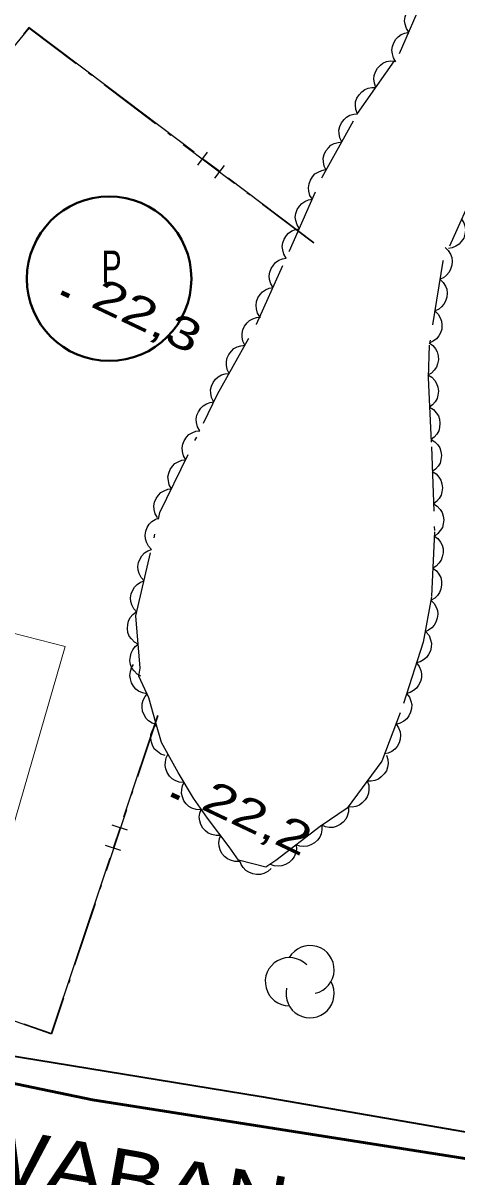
# Model space of a CAD drawing. Extents: x 356765 to 358572, y 5103174 to 5104650.
# Drawn here: x 357365.7 to 357385.9, y 5103762.5 to 5103816.2 of the extents above; entities that cross this region are included whole.
import ezdxf

# ---------------------------------------------------------------- set-up
doc = ezdxf.new("R2010")
doc.units = 0
doc.header["$LTSCALE"] = 0.6
doc.linetypes.add('DOT_DASHED', pattern=[7.7, 5, -1.2, 0.3, -1.2])
for name, color, linetype, lineweight in [('19', 7, 'Continuous', 13), ('21', 7, 'Continuous', 53), ('22', 7, 'Continuous', 35), ('3', 7, 'Continuous', 140), ('37', 7, 'Continuous', 13), ('38', 7, 'Continuous', 40), ('44', 7, 'Continuous', 25)]:
    doc.layers.add(name, color=color, linetype=linetype, lineweight=lineweight)

msp = doc.modelspace()

# ---------------------------------------------------------------- linework, layer by layer
at = {"layer": '19'}
msp.add_lwpolyline([(357362.8, 5103788.4), (357367.66, 5103787.16), (357362.28, 5103768.59)], dxfattribs=at)
at = {"layer": '21'}
msp.add_lwpolyline([(357338.61, 5103773.13), (357340.11, 5103772.62), (357343.3, 5103771.76), (357350.78, 5103769.83), (357368.94, 5103766.05), (357392.09, 5103762.41), (357416.79, 5103758.21), (357441.26, 5103754.15), (357468.58, 5103749.26), (357504.23, 5103742.99), (357523.34, 5103739.7), (357536.22, 5103737.01), (357542.95, 5103734.88), (357550.23, 5103731.38), (357559.17, 5103726.82), (357569.84, 5103720.84), (357583.91, 5103712.01), (357595.28, 5103704.43), (357600.89, 5103700.45), (357609.42, 5103694), (357620.2, 5103685.76)], dxfattribs=at)
at = {"layer": '22'}
msp.add_lwpolyline([(357366.39, 5103817.9), (357352.43, 5103801.73), (357349.01, 5103796), (357343.68, 5103784.65), (357339.63, 5103776.15), (357339.17, 5103775.09), (357339.32, 5103774.54), (357339.69, 5103774.25), (357340.1, 5103774.03), (357347.23, 5103771.98), (357356.47, 5103769.58), (357363.96, 5103768.3), (357376.79, 5103766.21), (357395.27, 5103763.01), (357430.46, 5103757.15), (357465, 5103751.32), (357465.88, 5103751.18), (357468.95, 5103750.64), (357513.48, 5103742.84)], dxfattribs=at)
at = {"layer": '3'}
for p, q in [((357367.49, 5103803.65), (357367.85, 5103803.48)), ((357372.62, 5103780.27), (357372.98, 5103780.1))]:
    msp.add_line(p, q, dxfattribs=at)
at = {"layer": '37', "lineweight": 25}
for p, q in [((357373.67, 5103810.18), (357369.68, 5103813.19)), ((357373.84, 5103809.58), (357374.29, 5103810.18)), ((357374.86, 5103809.28), (357374.06, 5103809.88)), ((357374.64, 5103808.98), (357375.09, 5103809.57)), ((357379.25, 5103805.96), (357375.26, 5103808.97)), ((357371.96, 5103783.95), (357370.38, 5103779.21)), ((357370.57, 5103778.61), (357369.86, 5103778.85)), ((357370.22, 5103778.73), (357369.9, 5103777.78)), ((357370.26, 5103777.66), (357369.54, 5103777.9)), ((357369.74, 5103777.31), (357368.16, 5103772.57))]:
    msp.add_line(p, q, dxfattribs=at)
at = {"layer": '37', "linetype": 'DOT_DASHED', "lineweight": 25}
for points in [[(357379.24, 5103805.94), (357365.98, 5103815.96), (357350.85, 5103797.63), (357349.13, 5103795.01), (357343.36, 5103779.3), (357342.98, 5103776.7), (357343.51, 5103775.15), (357358.16, 5103771.26)], [(357371.98, 5103783.94), (357367.03, 5103769.11), (357362.72, 5103770.63)]]:
    msp.add_lwpolyline(points, dxfattribs=at)
at = {"layer": '37', "lineweight": 25}
for points in [[(357369.68, 5103813.19), (357365.98, 5103815.99), (357365.72, 5103815.68)], [(357368.16, 5103772.57), (357367.02, 5103769.14), (357365.75, 5103769.58)]]:
    msp.add_lwpolyline(points, dxfattribs=at)
at = {"layer": '38'}
msp.add_circle((357369.7129, 5103804.2931), 3.8299, dxfattribs=at)
at = {"layer": '44', "linetype": 'DOT_DASHED'}
for points in [[(357371.1, 5103785.78), (357371.16, 5103786.16), (357370.96, 5103788.6), (357372.08, 5103793.41), (357374.76, 5103798.91), (357376.58, 5103802.17), (357378.11, 5103805.59), (357379.63, 5103809.02), (357381.28, 5103811.98), (357383.23, 5103814.78), (357384.59, 5103817.91)], [(357386.78, 5103808.54), (357385.25, 5103805.11), (357384.62, 5103801.19), (357384.56, 5103799.67), (357384.72, 5103796.47), (357384.86, 5103792.51), (357384.72, 5103789.48), (357384.33, 5103787.37), (357383.27, 5103784.07), (357382.41, 5103781.83), (357380.79, 5103779.63), (357379.53, 5103778.78), (357377.48, 5103777.2), (357377.01, 5103776.89), (357375.73, 5103777.21), (357375.3, 5103777.83), (357374.29, 5103779.17), (357373.64, 5103780.11), (357372.93, 5103781.29), (357372.15, 5103782.69), (357371.89, 5103783.61), (357371.56, 5103784.77), (357371.1, 5103785.78)]]:
    msp.add_lwpolyline(points, dxfattribs=at)
at = {"layer": '44'}
for points in [[(357383.66, 5103815.77), (357383.55, 5103815.94), (357383.49, 5103816.14), (357383.47, 5103816.3), (357383.5, 5103816.48), (357383.56, 5103816.65), (357383.66, 5103816.81), (357383.76, 5103816.94), (357383.91, 5103817.04), (357384.08, 5103817.11), (357384.26, 5103817.14)], [(357383.06, 5103814.39), (357382.95, 5103814.57), (357382.9, 5103814.76), (357382.87, 5103814.93), (357382.9, 5103815.1), (357382.96, 5103815.28), (357383.06, 5103815.44), (357383.17, 5103815.56), (357383.31, 5103815.66), (357383.48, 5103815.73), (357383.66, 5103815.77)], [(357382.13, 5103813.2), (357382.06, 5103813.4), (357382.04, 5103813.6), (357382.05, 5103813.76), (357382.11, 5103813.93), (357382.2, 5103814.09), (357382.34, 5103814.23), (357382.46, 5103814.33), (357382.63, 5103814.4), (357382.81, 5103814.44), (357382.99, 5103814.43)], [(357381.27, 5103811.97), (357381.2, 5103812.17), (357381.18, 5103812.37), (357381.19, 5103812.53), (357381.25, 5103812.7), (357381.35, 5103812.86), (357381.48, 5103813), (357381.61, 5103813.1), (357381.77, 5103813.16), (357381.95, 5103813.2), (357382.13, 5103813.2)], [(357380.54, 5103810.66), (357380.45, 5103810.85), (357380.42, 5103811.05), (357380.41, 5103811.21), (357380.45, 5103811.38), (357380.53, 5103811.55), (357380.65, 5103811.7), (357380.76, 5103811.82), (357380.92, 5103811.9), (357381.1, 5103811.96), (357381.27, 5103811.97)], [(357379.81, 5103809.35), (357379.72, 5103809.54), (357379.69, 5103809.74), (357379.68, 5103809.9), (357379.72, 5103810.07), (357379.8, 5103810.24), (357379.92, 5103810.39), (357380.03, 5103810.51), (357380.19, 5103810.59), (357380.37, 5103810.64), (357380.54, 5103810.66)], [(357379.18, 5103807.99), (357379.06, 5103808.17), (357379.01, 5103808.37), (357378.99, 5103808.53), (357379.02, 5103808.71), (357379.08, 5103808.88), (357379.18, 5103809.04), (357379.29, 5103809.17), (357379.44, 5103809.26), (357379.61, 5103809.33), (357379.78, 5103809.37)], [(357378.57, 5103806.62), (357378.46, 5103806.8), (357378.4, 5103807), (357378.38, 5103807.16), (357378.41, 5103807.33), (357378.47, 5103807.51), (357378.58, 5103807.67), (357378.68, 5103807.79), (357378.83, 5103807.89), (357379, 5103807.96), (357379.18, 5103807.99)], [(357377.96, 5103805.25), (357377.85, 5103805.43), (357377.8, 5103805.63), (357377.77, 5103805.79), (357377.8, 5103805.96), (357377.86, 5103806.14), (357377.97, 5103806.3), (357378.07, 5103806.42), (357378.22, 5103806.52), (357378.39, 5103806.59), (357378.57, 5103806.62)], [(357386.12, 5103807.07), (357386.23, 5103806.89), (357386.29, 5103806.7), (357386.31, 5103806.53), (357386.28, 5103806.36), (357386.22, 5103806.18), (357386.11, 5103806.02), (357386.01, 5103805.9), (357385.86, 5103805.8), (357385.69, 5103805.73), (357385.51, 5103805.7)], [(357385.35, 5103805.75), (357385.5, 5103805.61), (357385.61, 5103805.43), (357385.67, 5103805.28), (357385.69, 5103805.1), (357385.67, 5103804.92), (357385.61, 5103804.74), (357385.54, 5103804.59), (357385.42, 5103804.46), (357385.28, 5103804.34), (357385.11, 5103804.27)], [(357377.35, 5103803.88), (357377.24, 5103804.06), (357377.18, 5103804.26), (357377.16, 5103804.42), (357377.19, 5103804.59), (357377.25, 5103804.77), (357377.36, 5103804.93), (357377.46, 5103805.05), (357377.61, 5103805.15), (357377.78, 5103805.22), (357377.96, 5103805.25)], [(357385.11, 5103804.27), (357385.27, 5103804.12), (357385.37, 5103803.95), (357385.43, 5103803.8), (357385.45, 5103803.62), (357385.43, 5103803.44), (357385.37, 5103803.25), (357385.3, 5103803.11), (357385.19, 5103802.98), (357385.04, 5103802.86), (357384.88, 5103802.79)], [(357376.73, 5103802.51), (357376.62, 5103802.69), (357376.57, 5103802.89), (357376.55, 5103803.05), (357376.58, 5103803.23), (357376.64, 5103803.4), (357376.75, 5103803.56), (357376.85, 5103803.68), (357377, 5103803.78), (357377.17, 5103803.85), (357377.35, 5103803.88)], [(357376.03, 5103801.19), (357375.94, 5103801.38), (357375.9, 5103801.58), (357375.9, 5103801.74), (357375.94, 5103801.91), (357376.02, 5103802.08), (357376.14, 5103802.23), (357376.25, 5103802.34), (357376.41, 5103802.43), (357376.58, 5103802.48), (357376.76, 5103802.5)], [(357384.88, 5103802.79), (357385.03, 5103802.64), (357385.13, 5103802.47), (357385.19, 5103802.31), (357385.21, 5103802.14), (357385.2, 5103801.95), (357385.14, 5103801.77), (357385.07, 5103801.63), (357384.95, 5103801.5), (357384.8, 5103801.38), (357384.64, 5103801.31)], [(357384.62, 5103801.31), (357384.79, 5103801.18), (357384.91, 5103801.02), (357384.99, 5103800.88), (357385.03, 5103800.7), (357385.04, 5103800.52), (357385, 5103800.33), (357384.95, 5103800.18), (357384.85, 5103800.03), (357384.72, 5103799.9), (357384.57, 5103799.81)], [(357375.3, 5103799.88), (357375.21, 5103800.07), (357375.17, 5103800.27), (357375.17, 5103800.43), (357375.21, 5103800.6), (357375.29, 5103800.77), (357375.41, 5103800.92), (357375.52, 5103801.04), (357375.68, 5103801.12), (357375.85, 5103801.17), (357376.03, 5103801.19)], [(357374.57, 5103798.57), (357374.48, 5103798.76), (357374.44, 5103798.96), (357374.43, 5103799.12), (357374.48, 5103799.29), (357374.55, 5103799.46), (357374.67, 5103799.61), (357374.79, 5103799.73), (357374.95, 5103799.81), (357375.12, 5103799.86), (357375.3, 5103799.88)], [(357384.55, 5103799.81), (357384.73, 5103799.7), (357384.87, 5103799.55), (357384.96, 5103799.41), (357385.01, 5103799.24), (357385.04, 5103799.06), (357385.02, 5103798.87), (357384.98, 5103798.71), (357384.89, 5103798.56), (357384.77, 5103798.42), (357384.63, 5103798.31)], [(357373.93, 5103797.21), (357373.83, 5103797.39), (357373.78, 5103797.59), (357373.77, 5103797.75), (357373.8, 5103797.93), (357373.87, 5103798.1), (357373.98, 5103798.26), (357374.09, 5103798.38), (357374.24, 5103798.47), (357374.41, 5103798.53), (357374.59, 5103798.56)], [(357384.63, 5103798.31), (357384.81, 5103798.2), (357384.94, 5103798.05), (357385.04, 5103797.91), (357385.09, 5103797.75), (357385.11, 5103797.56), (357385.09, 5103797.37), (357385.06, 5103797.21), (357384.97, 5103797.06), (357384.85, 5103796.92), (357384.7, 5103796.81)], [(357373.28, 5103795.86), (357373.17, 5103796.04), (357373.13, 5103796.24), (357373.11, 5103796.41), (357373.14, 5103796.58), (357373.21, 5103796.75), (357373.32, 5103796.91), (357373.43, 5103797.03), (357373.58, 5103797.12), (357373.75, 5103797.19), (357373.93, 5103797.21)], [(357384.71, 5103796.81), (357384.88, 5103796.7), (357385.02, 5103796.55), (357385.11, 5103796.41), (357385.16, 5103796.24), (357385.18, 5103796.06), (357385.16, 5103795.87), (357385.12, 5103795.71), (357385.03, 5103795.56), (357384.91, 5103795.42), (357384.76, 5103795.31)], [(357372.62, 5103794.51), (357372.51, 5103794.7), (357372.47, 5103794.89), (357372.45, 5103795.06), (357372.49, 5103795.23), (357372.55, 5103795.4), (357372.66, 5103795.56), (357372.77, 5103795.68), (357372.92, 5103795.77), (357373.1, 5103795.84), (357373.28, 5103795.86)], [(357384.76, 5103795.31), (357384.94, 5103795.2), (357385.07, 5103795.05), (357385.16, 5103794.91), (357385.21, 5103794.74), (357385.24, 5103794.56), (357385.21, 5103794.37), (357385.17, 5103794.21), (357385.08, 5103794.06), (357384.96, 5103793.92), (357384.81, 5103793.81)], [(357371.96, 5103793.17), (357371.86, 5103793.35), (357371.81, 5103793.54), (357371.8, 5103793.71), (357371.83, 5103793.88), (357371.9, 5103794.05), (357372.01, 5103794.21), (357372.12, 5103794.33), (357372.27, 5103794.42), (357372.44, 5103794.49), (357372.62, 5103794.51)], [(357384.81, 5103793.81), (357384.99, 5103793.7), (357385.12, 5103793.55), (357385.22, 5103793.41), (357385.27, 5103793.24), (357385.29, 5103793.06), (357385.26, 5103792.87), (357385.23, 5103792.71), (357385.13, 5103792.56), (357385.01, 5103792.42), (357384.87, 5103792.31)], [(357371.68, 5103791.68), (357371.54, 5103791.84), (357371.45, 5103792.02), (357371.4, 5103792.18), (357371.39, 5103792.35), (357371.42, 5103792.54), (357371.49, 5103792.71), (357371.57, 5103792.86), (357371.7, 5103792.98), (357371.85, 5103793.08), (357372.02, 5103793.15)], [(357384.85, 5103792.31), (357385.02, 5103792.19), (357385.14, 5103792.03), (357385.22, 5103791.88), (357385.26, 5103791.71), (357385.26, 5103791.52), (357385.22, 5103791.34), (357385.17, 5103791.18), (357385.07, 5103791.04), (357384.94, 5103790.91), (357384.78, 5103790.82)], [(357371.34, 5103790.22), (357371.2, 5103790.38), (357371.11, 5103790.56), (357371.06, 5103790.72), (357371.05, 5103790.89), (357371.08, 5103791.08), (357371.15, 5103791.25), (357371.23, 5103791.39), (357371.36, 5103791.52), (357371.51, 5103791.62), (357371.68, 5103791.68)], [(357384.78, 5103790.82), (357384.95, 5103790.69), (357385.07, 5103790.53), (357385.15, 5103790.38), (357385.19, 5103790.21), (357385.19, 5103790.03), (357385.15, 5103789.84), (357385.1, 5103789.68), (357385, 5103789.54), (357384.87, 5103789.41), (357384.71, 5103789.32)], [(357371, 5103788.76), (357370.86, 5103788.92), (357370.77, 5103789.1), (357370.72, 5103789.26), (357370.71, 5103789.43), (357370.74, 5103789.61), (357370.81, 5103789.79), (357370.89, 5103789.93), (357371.02, 5103790.06), (357371.17, 5103790.16), (357371.34, 5103790.22)], [(357384.69, 5103789.32), (357384.84, 5103789.17), (357384.94, 5103789), (357385, 5103788.84), (357385.01, 5103788.67), (357384.99, 5103788.48), (357384.93, 5103788.3), (357384.85, 5103788.16), (357384.73, 5103788.03), (357384.58, 5103787.92), (357384.42, 5103787.85)], [(357371.07, 5103787.27), (357370.89, 5103787.37), (357370.75, 5103787.52), (357370.65, 5103787.65), (357370.59, 5103787.82), (357370.56, 5103788), (357370.58, 5103788.19), (357370.61, 5103788.35), (357370.69, 5103788.51), (357370.81, 5103788.65), (357370.95, 5103788.77)], [(357384.48, 5103787.83), (357384.61, 5103787.67), (357384.68, 5103787.48), (357384.72, 5103787.32), (357384.71, 5103787.14), (357384.67, 5103786.96), (357384.58, 5103786.79), (357384.49, 5103786.65), (357384.35, 5103786.54), (357384.19, 5103786.45), (357384.02, 5103786.4)], [(357371.19, 5103785.78), (357371.01, 5103785.88), (357370.87, 5103786.03), (357370.77, 5103786.16), (357370.71, 5103786.33), (357370.68, 5103786.51), (357370.7, 5103786.7), (357370.73, 5103786.86), (357370.81, 5103787.01), (357370.93, 5103787.16), (357371.07, 5103787.27)], [(357371.47, 5103784.96), (357371.27, 5103785), (357371.08, 5103785.09), (357370.95, 5103785.18), (357370.84, 5103785.32), (357370.75, 5103785.48), (357370.7, 5103785.66), (357370.67, 5103785.82), (357370.7, 5103786), (357370.76, 5103786.17), (357370.85, 5103786.33)], [(357384.02, 5103786.4), (357384.15, 5103786.24), (357384.22, 5103786.05), (357384.26, 5103785.89), (357384.25, 5103785.71), (357384.21, 5103785.53), (357384.12, 5103785.36), (357384.03, 5103785.23), (357383.89, 5103785.12), (357383.73, 5103785.02), (357383.56, 5103784.97)], [(357371.91, 5103783.53), (357371.71, 5103783.6), (357371.55, 5103783.71), (357371.43, 5103783.82), (357371.34, 5103783.98), (357371.27, 5103784.15), (357371.25, 5103784.34), (357371.25, 5103784.5), (357371.3, 5103784.67), (357371.39, 5103784.84), (357371.5, 5103784.97)], [(357383.56, 5103784.97), (357383.69, 5103784.81), (357383.76, 5103784.62), (357383.8, 5103784.46), (357383.79, 5103784.28), (357383.75, 5103784.1), (357383.66, 5103783.93), (357383.57, 5103783.8), (357383.44, 5103783.69), (357383.27, 5103783.6), (357383.1, 5103783.55)], [(357372.32, 5103782.09), (357372.12, 5103782.15), (357371.96, 5103782.27), (357371.83, 5103782.38), (357371.75, 5103782.53), (357371.68, 5103782.71), (357371.66, 5103782.9), (357371.66, 5103783.06), (357371.71, 5103783.23), (357371.8, 5103783.39), (357371.91, 5103783.53)], [(357383.07, 5103783.56), (357383.19, 5103783.38), (357383.26, 5103783.19), (357383.28, 5103783.03), (357383.27, 5103782.85), (357383.21, 5103782.68), (357383.12, 5103782.51), (357383.02, 5103782.38), (357382.88, 5103782.28), (357382.71, 5103782.2), (357382.53, 5103782.16)], [(357373.18, 5103780.83), (357372.98, 5103780.85), (357372.79, 5103780.93), (357372.64, 5103781.01), (357372.52, 5103781.13), (357372.42, 5103781.29), (357372.35, 5103781.47), (357372.32, 5103781.63), (357372.33, 5103781.8), (357372.37, 5103781.98), (357372.45, 5103782.14)], [(357382.62, 5103782.11), (357382.69, 5103781.91), (357382.7, 5103781.71), (357382.68, 5103781.55), (357382.62, 5103781.38), (357382.52, 5103781.23), (357382.38, 5103781.09), (357382.25, 5103780.99), (357382.09, 5103780.93), (357381.91, 5103780.9), (357381.73, 5103780.9)], [(357373.97, 5103779.56), (357373.76, 5103779.57), (357373.57, 5103779.64), (357373.43, 5103779.71), (357373.3, 5103779.84), (357373.19, 5103779.98), (357373.12, 5103780.16), (357373.08, 5103780.32), (357373.09, 5103780.5), (357373.12, 5103780.68), (357373.2, 5103780.84)], [(357381.73, 5103780.9), (357381.8, 5103780.71), (357381.81, 5103780.5), (357381.79, 5103780.34), (357381.73, 5103780.17), (357381.63, 5103780.02), (357381.49, 5103779.88), (357381.37, 5103779.78), (357381.2, 5103779.72), (357381.02, 5103779.69), (357380.84, 5103779.7)], [(357374.89, 5103778.37), (357374.69, 5103778.36), (357374.49, 5103778.41), (357374.33, 5103778.47), (357374.2, 5103778.58), (357374.07, 5103778.71), (357373.98, 5103778.88), (357373.93, 5103779.04), (357373.91, 5103779.21), (357373.93, 5103779.4), (357373.99, 5103779.57)], [(357380.86, 5103779.68), (357380.86, 5103779.47), (357380.8, 5103779.27), (357380.73, 5103779.12), (357380.61, 5103778.99), (357380.47, 5103778.87), (357380.29, 5103778.79), (357380.14, 5103778.74), (357379.96, 5103778.74), (357379.78, 5103778.77), (357379.61, 5103778.84)], [(357379.61, 5103778.84), (357379.62, 5103778.63), (357379.58, 5103778.44), (357379.52, 5103778.28), (357379.41, 5103778.14), (357379.27, 5103778.02), (357379.1, 5103777.93), (357378.95, 5103777.87), (357378.78, 5103777.85), (357378.59, 5103777.87), (357378.42, 5103777.93)], [(357375.77, 5103777.15), (357375.56, 5103777.15), (357375.37, 5103777.21), (357375.22, 5103777.27), (357375.08, 5103777.39), (357374.96, 5103777.53), (357374.88, 5103777.7), (357374.83, 5103777.86), (357374.82, 5103778.03), (357374.85, 5103778.22), (357374.92, 5103778.38)], [(357378.42, 5103777.93), (357378.43, 5103777.72), (357378.39, 5103777.52), (357378.33, 5103777.37), (357378.22, 5103777.23), (357378.09, 5103777.1), (357377.92, 5103777.01), (357377.76, 5103776.95), (357377.59, 5103776.94), (357377.4, 5103776.95), (357377.23, 5103777.01)], [(357377.25, 5103776.83), (357377.1, 5103776.69), (357376.91, 5103776.6), (357376.76, 5103776.55), (357376.58, 5103776.55), (357376.4, 5103776.58), (357376.22, 5103776.66), (357376.08, 5103776.74), (357375.96, 5103776.87), (357375.86, 5103777.02), (357375.8, 5103777.19)]]:
    msp.add_lwpolyline(points, dxfattribs=at)
for centre, start, end in [((357379.0688, 5103772.1167), 282.26917, 149.72626), ((357378.1035, 5103771.5555), 44.11537, 269.80396), ((357379.0688, 5103770.9943), 166.93686, 29.62122)]:
    msp.add_arc(centre, 1.1224, start, end, dxfattribs=at)

# ---------------------------------------------------------------- texts
at = {"layer": '21', "width": 1.2}
msp.add_text('RUE WABAN AKI', height=2.6, rotation=350.126, dxfattribs=at).set_placement((357352.89, 5103764.18))
at = {"layer": '3', "width": 1.35}
for s, p in [('22,3   ', (357368.79, 5103803.02)), ('22,2   ', (357373.92, 5103779.63))]:
    msp.add_text(s, height=1.5, rotation=334.619, dxfattribs=at).set_placement(p)
at = {"layer": '38', "width": 0.7}
msp.add_text('P', height=1.5, dxfattribs=at).set_placement((357369.36, 5103804.1))

doc.saveas('drawing.dxf')
